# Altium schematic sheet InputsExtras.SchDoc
size A4
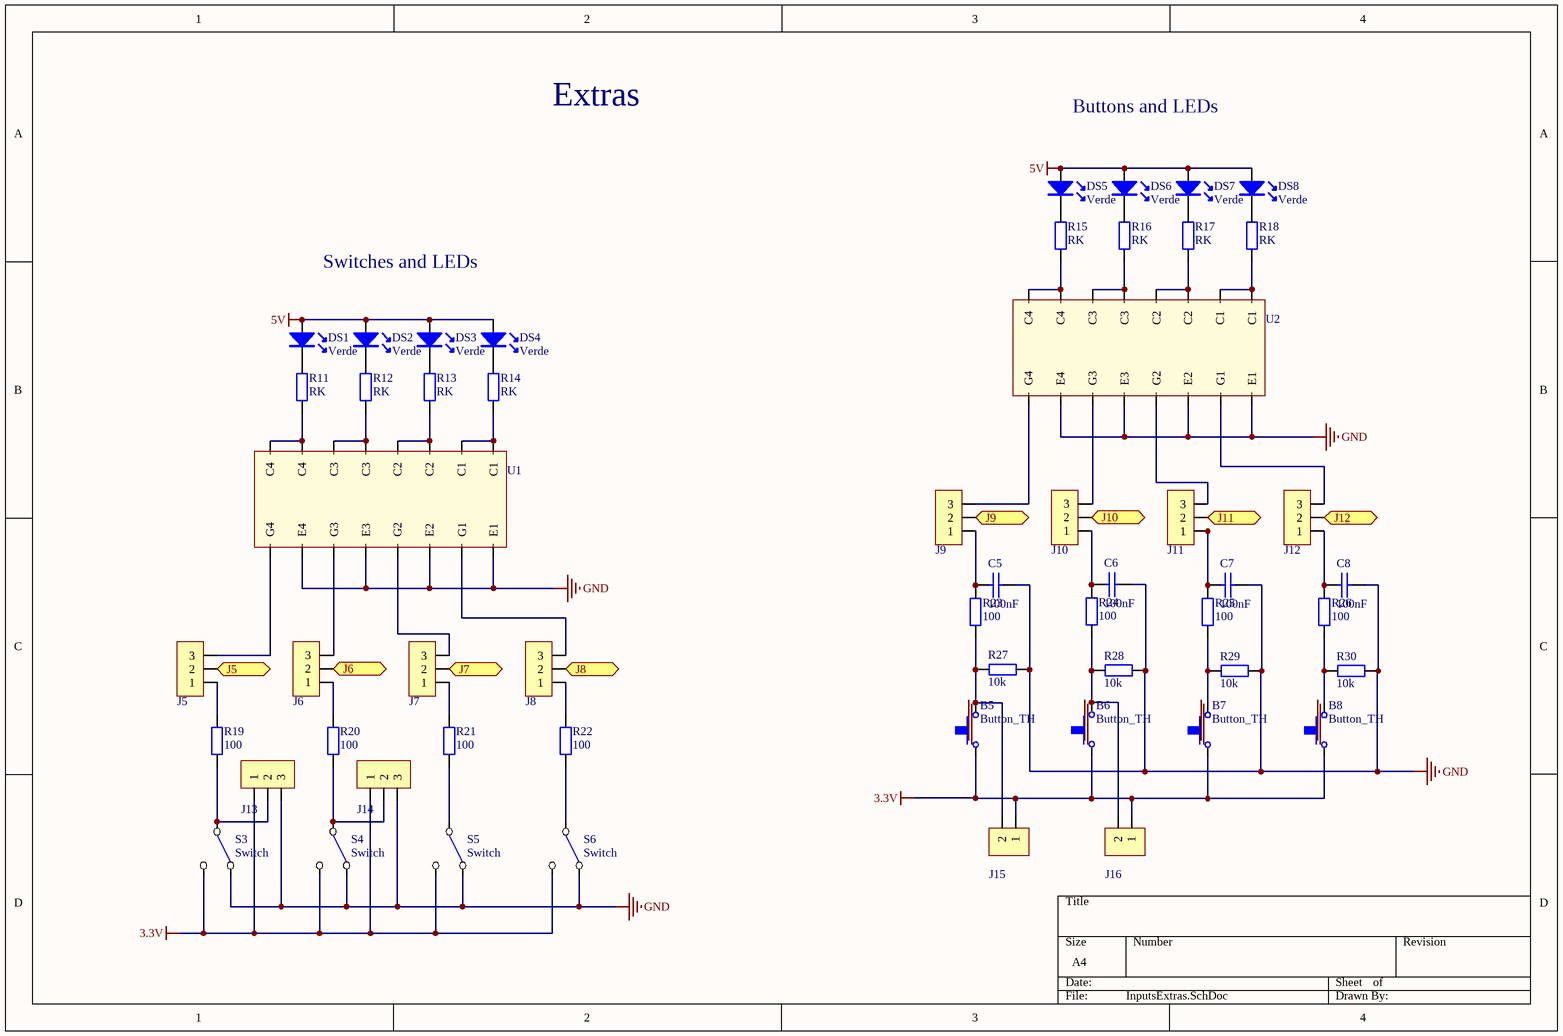
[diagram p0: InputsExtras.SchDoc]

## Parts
B5  Button_TH  [ButtonTH]
B6  Button_TH  [ButtonTH]
B7  Button_TH  [ButtonTH]
B8  Button_TH  [ButtonTH]
C5  100nF  [1206]
C6  100nF  [1206]
C7  100nF  [1206]
C8  100nF  [1206]
DS1  Verde  [LED_100mil]
DS2  Verde  [LED_100mil]
DS3  Verde  [LED_100mil]
DS4  Verde  [LED_100mil]
DS5  Verde  [LED_100mil]
DS6  Verde  [LED_100mil]
DS7  Verde  [LED_100mil]
DS8  Verde  [LED_100mil]
J5  Cleva 2 vias  [con_3_100milis]  (value not drawn)
J6  Cleva 2 vias  [con_3_100milis]  (value not drawn)
J7  Cleva 2 vias  [con_3_100milis]  (value not drawn)
J8  Cleva 2 vias  [con_3_100milis]  (value not drawn)
J9  Cleva 2 vias  [con_3_100milis]  (value not drawn)
J10  Cleva 2 vias  [con_3_100milis]  (value not drawn)
J11  Cleva 2 vias  [con_3_100milis]  (value not drawn)
J12  Cleva 2 vias  [con_3_100milis]  (value not drawn)
J13  Cleva 2 vias  [Con3_KK_256]  (value not drawn)
J14  Cleva 2 vias  [Con3_KK_256]  (value not drawn)
J15  Cleva 2 vias  [Con2_KK_256]  (value not drawn)
J16  Cleva 2 vias  [Con2_KK_256]  (value not drawn)
R11  RK  [1206]
R12  RK  [1206]
R13  RK  [1206]
R14  RK  [1206]
R15  RK  [1206]
R16  RK  [1206]
R17  RK  [1206]
R18  RK  [1206]
R19  100  [1206]
R20  100  [1206]
R21  100  [1206]
R22  100  [1206]
R23  100  [1206]
R24  100  [1206]
R25  100  [1206]
R26  100  [1206]
R27  10k  [1206]
R28  10k  [1206]
R29  10k  [1206]
R30  10k  [1206]
S3  Switch  [SwitchTH_2Pos]
S4  Switch  [SwitchTH_2Pos]
S5  Switch  [SwitchTH_2Pos]
S6  Switch  [SwitchTH_2Pos]
U1  MMPQ3904  [SO-16]  (value not drawn)
U2  MMPQ3904  [SO-16]  (value not drawn)

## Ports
J5, J6, J7, J8, J9, J10, J11, J12

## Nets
3.3V: B5.1 B6.1 B7.1 B8.1 J13.1 J14.1 J15.1 J16.1 S3.2(ON2) S4.2(ON2) S5.2(ON2) S6.2(ON2)
5V: DS1.A DS2.A DS3.A DS4.A DS5.A DS6.A DS7.A DS8.A
GND: C5.1 C6.1 C7.1 C8.1 J13.3 J14.3 R27.1 R28.1 R29.1 R30.1 S3.0(ON1) S4.0(ON1) S5.0(ON1) S6.0(ON1) U1.10(E4) U1.12(E3) U1.14(E2) U1.16(E1) U2.10(E4) U2.12(E3) U2.14(E2) U2.16(E1)
J5: J5.2 ; port J5
J6: J6.2 ; port J6
J7: J7.2 ; port J7
J8: J8.2 ; port J8
J9: J9.2 ; port J9
J10: J10.2 ; port J10
J11: J11.2 ; port J11
J12: J12.2 ; port J12
NetB5_0: B5.0 J15.2 R23.1 R27.2
NetB6_0: B6.0 J16.2 R24.1 R28.2
NetB7_0: B7.0 R25.1 R29.2
NetB8_0: B8.0 R26.1 R30.2
NetC5_2: C5.2 J9.1 R23.2
NetC6_2: C6.2 J10.1 R24.2
NetC7_2: C7.2 J11.1 R25.2
NetC8_2: C8.2 J12.1 R26.2
NetDS1_K: DS1.K R11.1
NetDS2_K: DS2.K R12.1
NetDS3_K: DS3.K R13.1
NetDS4_K: DS4.K R14.1
NetDS5_K: DS5.K R15.1
NetDS6_K: DS6.K R16.1
NetDS7_K: DS7.K R17.1
NetDS8_K: DS8.K R18.1
NetJ5_1: J5.1 R19.2
NetJ5_3: J5.3 U1.9(G4)
NetJ6_1: J6.1 R20.2
NetJ6_3: J6.3 U1.11(G3)
NetJ7_1: J7.1 R21.2
NetJ7_3: J7.3 U1.13(G2)
NetJ8_1: J8.1 R22.2
NetJ8_3: J8.3 U1.15(G1)
NetJ9_3: J9.3 U2.9(G4)
NetJ10_3: J10.3 U2.11(G3)
NetJ11_3: J11.3 U2.13(G2)
NetJ12_3: J12.3 U2.15(G1)
NetJ13_2: J13.2 R19.1 S3.1(COMMON)
NetJ14_2: J14.2 R20.1 S4.1(COMMON)
NetR11_2: R11.2 U1.7(C4) U1.8(C4)
NetR12_2: R12.2 U1.5(C3) U1.6(C3)
NetR13_2: R13.2 U1.3(C2) U1.4(C2)
NetR14_2: R14.2 U1.1(C1) U1.2(C1)
NetR15_2: R15.2 U2.7(C4) U2.8(C4)
NetR16_2: R16.2 U2.5(C3) U2.6(C3)
NetR17_2: R17.2 U2.3(C2) U2.4(C2)
NetR18_2: R18.2 U2.1(C1) U2.2(C1)
NetR21_1: R21.1 S5.1(COMMON)
NetR22_1: R22.1 S6.1(COMMON)

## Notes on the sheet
- Extras
- Buttons and LEDs
- Switches and LEDs

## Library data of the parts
C5-C8 = Condensador
DS1-DS8 = Led
J5-J14 = Con_3
J15 J16 = Con_2
R11-R30 = Resistencia: Potencia: 1/4W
